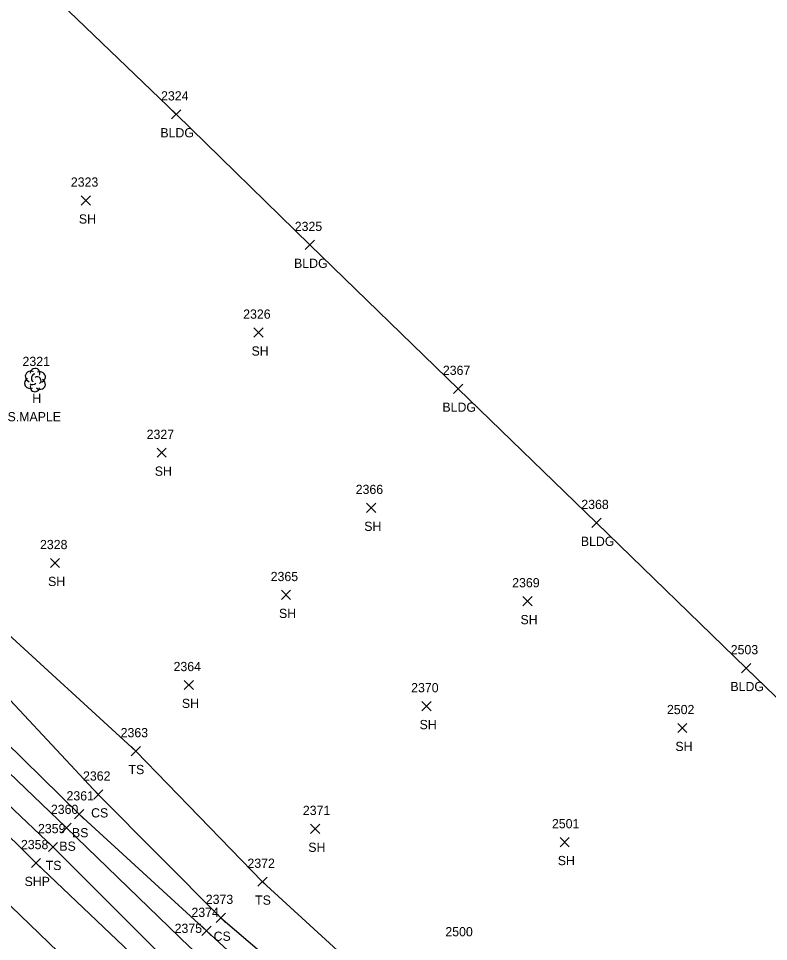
# Model space of a CAD drawing. Extents: x 1472233 to 1475777, y 540726 to 543442.
# Drawn here: x 1473678.6 to 1473841.3, y 542599.7 to 542800 of the extents above; entities that cross this region are included whole.
import ezdxf

# ---------------------------------------------------------------- set-up
doc = ezdxf.new("R2010")
doc.units = 0
for name, color, linetype in [('L_A', 7, 'Continuous'), ('L_C', 7, 'Continuous'), ('L_I', 7, 'Continuous'), ('L_TIC', 7, 'Continuous'), ('LBC', 7, 'Continuous'), ('LELB', 7, 'Continuous'), ('LSOGP', 7, 'Continuous'), ('LTD', 7, 'Continuous'), ('P_A', 7, 'Continuous'), ('P_I', 7, 'Continuous'), ('P_TIC', 7, 'Continuous'), ('PET', 7, 'Continuous'), ('PSP', 7, 'Continuous')]:
    doc.layers.add(name, color=color, linetype=linetype)

msp = doc.modelspace()

# ---------------------------------------------------------------- linework, layer by layer
at = {"layer": 'L_TIC'}
for points in [[(1473711.79, 542778.19), (1473713.79, 542780.19)], [(1473713.79, 542778.19), (1473711.79, 542780.19)], [(1473692.22, 542759.49), (1473694.22, 542761.49)], [(1473694.22, 542759.49), (1473692.22, 542761.49)], [(1473740.79, 542749.87), (1473742.79, 542751.87)], [(1473742.79, 542749.87), (1473740.79, 542751.87)], [(1473729.66, 542730.85), (1473731.66, 542732.85)], [(1473731.66, 542730.85), (1473729.66, 542732.85)], [(1473772.96, 542718.66), (1473774.96, 542720.66)], [(1473774.96, 542718.66), (1473772.96, 542720.66)], [(1473708.67, 542704.78), (1473710.67, 542706.78)], [(1473710.67, 542704.78), (1473708.67, 542706.78)], [(1473754.11, 542692.82), (1473756.11, 542694.82)], [(1473756.11, 542692.82), (1473754.11, 542694.82)], [(1473803, 542689.56), (1473805, 542691.56)], [(1473805, 542689.56), (1473803, 542691.56)], [(1473685.53, 542680.86), (1473687.53, 542682.86)], [(1473687.53, 542680.86), (1473685.53, 542682.86)], [(1473735.62, 542673.93), (1473737.62, 542675.93)], [(1473737.62, 542673.93), (1473735.62, 542675.93)], [(1473788.01, 542672.58), (1473790.01, 542674.58)], [(1473790.01, 542672.58), (1473788.01, 542674.58)], [(1473835.45, 542658.06), (1473837.45, 542660.06)], [(1473837.45, 542658.06), (1473835.45, 542660.06)], [(1473714.55, 542654.4), (1473716.55, 542656.4)], [(1473716.55, 542654.4), (1473714.55, 542656.4)], [(1473766.13, 542649.81), (1473768.13, 542651.81)], [(1473768.13, 542649.81), (1473766.13, 542651.81)], [(1473821.61, 542645.07), (1473823.61, 542647.07)], [(1473823.61, 542645.07), (1473821.61, 542647.07)], [(1473703.07, 542640.06), (1473705.07, 542642.06)], [(1473705.07, 542640.06), (1473703.07, 542642.06)], [(1473694.91, 542630.66), (1473696.91, 542632.66)], [(1473696.91, 542630.66), (1473694.91, 542632.66)], [(1473690.76, 542626.35), (1473692.76, 542628.35)], [(1473692.76, 542626.35), (1473690.76, 542628.35)], [(1473688.02, 542623.42), (1473690.02, 542625.42)], [(1473690.02, 542623.42), (1473688.02, 542625.42)], [(1473741.98, 542623.19), (1473743.98, 542625.19)], [(1473743.98, 542623.19), (1473741.98, 542625.19)], [(1473796.09, 542620.31), (1473798.09, 542622.31)], [(1473798.09, 542620.31), (1473796.09, 542622.31)], [(1473685.09, 542619.25), (1473687.09, 542621.25)], [(1473687.09, 542619.25), (1473685.09, 542621.25)], [(1473730.53, 542611.73), (1473732.53, 542613.73)], [(1473732.53, 542611.73), (1473730.53, 542613.73)], [(1473721.49, 542603.9), (1473723.49, 542605.9)], [(1473723.49, 542603.9), (1473721.49, 542605.9)], [(1473718.38, 542601.08), (1473720.38, 542603.08)], [(1473720.38, 542601.08), (1473718.38, 542603.08)]]:
    msp.add_lwpolyline(points, dxfattribs=at)
at = {"layer": 'LBC'}
msp.add_lwpolyline([(1473611.81, 542877.43), (1473647.84, 542842.15), (1473684.15, 542806.79), (1473712.79, 542779.19), (1473741.79, 542750.87), (1473773.96, 542719.66), (1473804, 542690.56), (1473836.45, 542659.06), (1473871.86, 542624.85), (1473901.94, 542656.08), (1473913.55, 542668.06), (1473934.21, 542647.92), (1473934.79, 542648.35), (1473977.15, 542693.11), (1473991.17, 542706.54), (1473991.24, 542706.56), (1473999.37, 542698.9), (1474013.8, 542713.45), (1473985.08, 542741.69), (1474015.74, 542773.16), (1474040.72, 542798.97), (1474028.75, 542810.8)], dxfattribs=at)
at = {"layer": 'LELB'}
for points in [[(1473533.67, 542804.55), (1473552.88, 542788.13), (1473556.88, 542785.23), (1473573.99, 542766.25), (1473612.39, 542727.62), (1473636.32, 542702.27), (1473673.71, 542668.77), (1473704.07, 542641.06), (1473731.53, 542612.73), (1473761.48, 542585.32), (1473782.29, 542564.92), (1473785.92, 542561.45), (1473799.65, 542550.04), (1473837.85, 542540.63), (1473852.25, 542543.24), (1473872.66, 542564.42), (1473894.27, 542588.71), (1473912.61, 542619.34)], [(1473525.71, 542797.41), (1473571.76, 542752.99), (1473604.17, 542719.3), (1473629.42, 542695.86), (1473668.69, 542660.73), (1473695.91, 542631.66), (1473722.49, 542604.9), (1473754.1, 542577.93), (1473792.77, 542542.66), (1473824.81, 542525.66)], [(1473520.98, 542792.82), (1473566.75, 542747.64), (1473598.73, 542714.04), (1473624.71, 542692.05), (1473663.48, 542655.08), (1473691.76, 542627.35), (1473719.38, 542602.08), (1473749.67, 542574.18), (1473788.77, 542538.46), (1473824.81, 542525.66), (1473852.8, 542532.76), (1473882.6, 542548.46), (1473905.87, 542578.34), (1473927.53, 542599.64)], [(1473518.4, 542790.01), (1473563.89, 542744.47), (1473596.86, 542712.19), (1473621.23, 542688.95), (1473660.33, 542651.88), (1473689.02, 542624.42), (1473715.73, 542598.61), (1473746.44, 542571.32), (1473784.75, 542534.69), (1473817.99, 542514.69), (1473848.43, 542502.42), (1473876.97, 542512.66), (1473897.43, 542533.79), (1473923.6, 542558.96), (1473938.44, 542588.81), (1473927.53, 542599.64)], [(1473514.27, 542786.32), (1473560.24, 542740.99), (1473594.17, 542708.93), (1473617.93, 542685.84), (1473656.3, 542648.39), (1473686.09, 542620.25), (1473711.9, 542594.5), (1473742.08, 542567.84), (1473780.05, 542529.89), (1473807.97, 542506.72), (1473829.24, 542487.77), (1473845.46, 542486.06), (1473857.71, 542489.19), (1473866.44, 542494.63), (1473880.47, 542509.49), (1473900.34, 542530.71), (1473925.82, 542557.03), (1473946.47, 542580.98), (1473946.59, 542594.08), (1473931.4, 542613.43), (1473912.61, 542619.34)]]:
    msp.add_lwpolyline(points, dxfattribs=at)
at = {"layer": 'LSOGP'}
msp.add_lwpolyline([(1473684.15, 542806.79), (1473712.79, 542779.19), (1473741.79, 542750.87), (1473773.96, 542719.66), (1473804, 542690.56), (1473836.45, 542659.06), (1473871.86, 542624.85), (1473901.94, 542656.08), (1473913.55, 542668.06), (1473934.21, 542647.92), (1473934.79, 542648.35), (1473977.15, 542693.11), (1473991.17, 542706.54), (1473991.24, 542706.56), (1473999.37, 542698.9), (1474013.8, 542713.45), (1473985.08, 542741.69), (1474015.74, 542773.16), (1474040.72, 542798.97), (1474028.75, 542810.8)], dxfattribs=at)
at = {"layer": 'LTD'}
msp.add_line((1473682.17, 542721.59), (1473682.17, 542721.59), dxfattribs=at)
msp.add_line((1473682.17, 542721.59), (1473682.17, 542721.59), dxfattribs=at)
msp.add_arc((1473682.21, 542723.03), 1.05, 335.5272, 180.9563, dxfattribs=at)
for centre, major_axis, ratio, start_param, end_param in [((1473681.37, 542722.26), (1.21, -0.51), 0.895232, 1.570796, 4.712389), ((1473681.96, 542722.05), (-0.208, -0.792), 0.645439, 3.141593, 6.283185), ((1473682.67, 542721.43), (-0.5, 0.667), 0.989748, 3.141593, 6.283185), ((1473683.21, 542722.18), (-1.14, -0.48), 0.949671, 1.570796, 4.712389), ((1473681.08, 542720.88), (0.58, -1.04), 0.959034, 3.141593, 6.283185), ((1473682.17, 542720.09), (0.26, 1.06), 0.942809, 1.570796, 4.712389), ((1473681.71, 542720.84), (-0.625, -0.083), 0.423636, 0, 3.141593), ((1473683.17, 542720.76), (-1.09, 0.79), 0.841452, 1.570796, 4.712389)]:
    msp.add_ellipse(centre, major_axis=major_axis, ratio=ratio, start_param=start_param, end_param=end_param, dxfattribs=at)
at = {"layer": 'P_TIC'}
for points in [[(1473681.39, 542615.78), (1473683.39, 542617.78)], [(1473683.39, 542615.78), (1473681.39, 542617.78)]]:
    msp.add_lwpolyline(points, dxfattribs=at)
at = {"layer": 'PET'}
msp.add_lwpolyline([(1473504.62, 542776.33), (1473550.32, 542731.61), (1473584.84, 542698.3), (1473608.01, 542675.08), (1473646.67, 542637.68), (1473674.93, 542609.37), (1473701.59, 542583.63), (1473729.62, 542555.98), (1473768.46, 542518.15), (1473803.13, 542483.63), (1473835.24, 542452.12), (1473854.12, 542434.15), (1473878.03, 542410.14), (1473913.11, 542376.24), (1473951.32, 542338.39), (1473966.93, 542323.54), (1474008.37, 542283), (1474040.51, 542251.21), (1474079.09, 542215.26), (1474152.53, 542143.43), (1474186.7, 542109.47), (1474221.34, 542076.07), (1474257.17, 542041.35)], dxfattribs=at)
at = {"layer": 'PSP'}
msp.add_lwpolyline([(1473511.53, 542783.65), (1473557.71, 542738.52), (1473591.71, 542705.85), (1473614.8, 542682.52), (1473653.25, 542645.69), (1473682.39, 542616.78), (1473708.77, 542591.71), (1473737.42, 542563.39), (1473776.1, 542525.9), (1473801.03, 542501.12), (1473821.16, 542481.55), (1473851.91, 542452.04), (1473882.06, 542422.12), (1473920.54, 542384.18), (1473958.97, 542346.58), (1473974.8, 542332.02), (1474016, 542291.37), (1474048.58, 542260.06), (1474087.68, 542221.94), (1474123.03, 542187.8), (1474161.37, 542151.41), (1474230.43, 542083.96), (1474265.44, 542049.86)], dxfattribs=at)

# ---------------------------------------------------------------- texts
at = {"layer": 'L_A'}
for s, p in [('BLDG', (1473709.38, 542774.19)), ('SH', (1473691.7, 542755.49)), ('BLDG', (1473738.38, 542745.87)), ('SH', (1473729.15, 542726.85)), ('H', (1473681.6, 542716.59)), ('BLDG', (1473770.56, 542714.66)), ('SH', (1473708.16, 542700.78)), ('SH', (1473753.6, 542688.82)), ('BLDG', (1473800.59, 542685.56)), ('SH', (1473685.02, 542676.86)), ('SH', (1473735.11, 542669.93)), ('SH', (1473787.5, 542668.58)), ('BLDG', (1473833.04, 542654.06)), ('SH', (1473714.04, 542650.4)), ('SH', (1473765.61, 542645.81)), ('SH', (1473821.1, 542641.07)), ('TS', (1473702.47, 542636.06)), ('CS', (1473694.35, 542626.66)), ('BS', (1473690.2, 542622.35)), ('BS', (1473687.46, 542619.42)), ('SH', (1473741.47, 542619.19)), ('SH', (1473795.58, 542616.31)), ('TS', (1473684.5, 542615.25)), ('TS', (1473729.94, 542607.73)), ('CS', (1473720.93, 542599.9))]:
    msp.add_text(s, height=2, dxfattribs=at).set_placement(p)
at = {"layer": 'L_C'}
msp.add_text('S.MAPLE', height=2, dxfattribs=at).set_placement((1473676.23, 542712.59))
at = {"layer": 'L_I'}
for s, p in [('2324', (1473709.53, 542782.19)), ('2323', (1473689.96, 542763.49)), ('2325', (1473738.53, 542753.87)), ('2326', (1473727.34, 542734.85)), ('2321', (1473679.47, 542724.59)), ('2367', (1473770.66, 542722.66)), ('2327', (1473706.41, 542708.78)), ('2366', (1473751.75, 542696.82)), ('2368', (1473800.69, 542693.56)), ('2328', (1473683.27, 542684.86)), ('2365', (1473733.31, 542677.93)), ('2369', (1473785.7, 542676.58)), ('2503', (1473833.11, 542662.06)), ('2364', (1473712.24, 542658.4)), ('2370', (1473763.78, 542653.81)), ('2502', (1473819.27, 542649.07)), ('2363', (1473700.76, 542644.06)), ('2362', (1473692.6, 542634.66)), ('2361', (1473689.02, 542630.35)), ('2360', (1473685.63, 542627.42)), ('2371', (1473740.29, 542627.19)), ('2501', (1473794.32, 542624.31)), ('2359', (1473682.83, 542623.25)), ('2372', (1473728.27, 542615.73)), ('2373', (1473719.23, 542607.9)), ('2374', (1473716.12, 542605.08)), ('2375', (1473712.47, 542601.61)), ('2500', (1473771.2, 542600.88))]:
    msp.add_text(s, height=2, dxfattribs=at).set_placement(p)
at = {"layer": 'P_A'}
msp.add_text('SHP', height=2, dxfattribs=at).set_placement((1473679.92, 542611.78))
at = {"layer": 'P_I'}
msp.add_text('2358', height=2, dxfattribs=at).set_placement((1473679.13, 542619.78))

doc.saveas('drawing.dxf')
